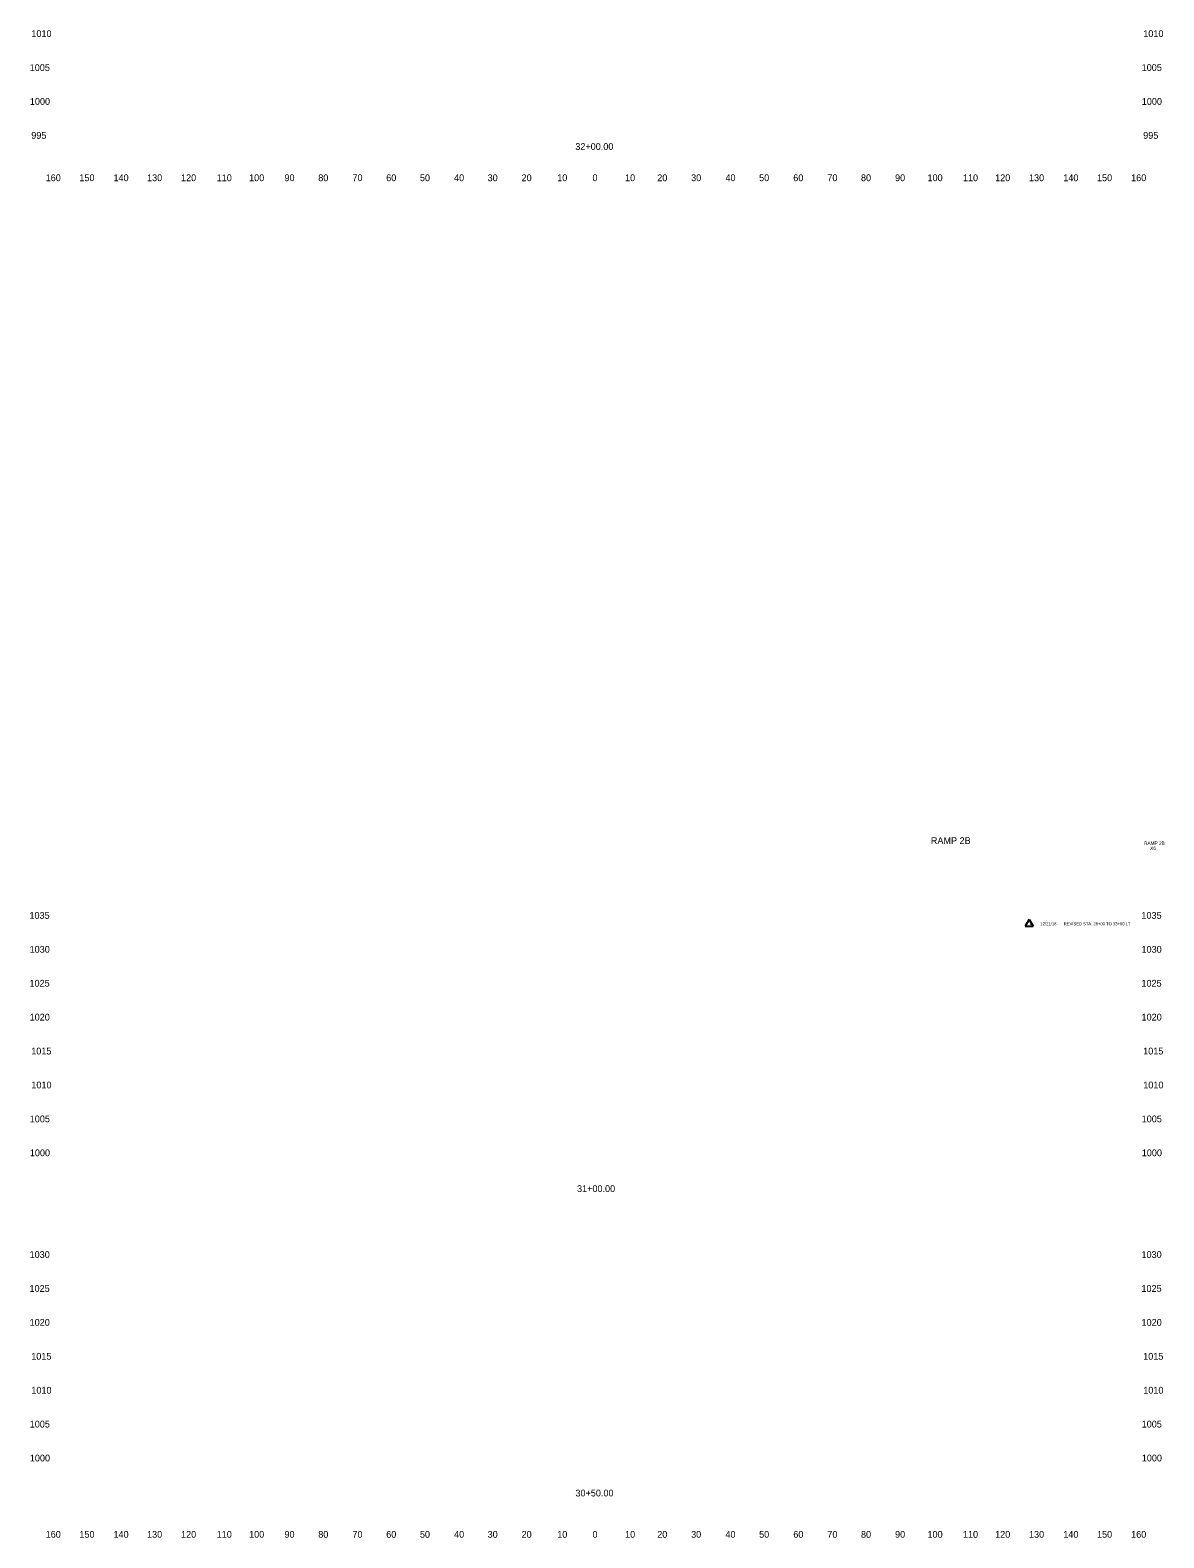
# Model space of a CAD drawing. Extents: x 4994 to 6358, y 4997 to 8804.
# Drawn here: x 4993.5 to 5327.7, y 6997.5 to 7442 of the extents above; entities that cross this region are included whole.
import ezdxf

# ---------------------------------------------------------------- set-up
doc = ezdxf.new("R2010")
doc.units = 0
for name, color, linetype in [('RD_SHT_ID', 7, 'Continuous'), ('RD_SHT_TX', 7, 'Continuous'), ('RD_XS_TX_Offset', 7, 'Continuous'), ('RD_XS_TX_Station', 7, 'Continuous')]:
    doc.layers.add(name, color=color, linetype=linetype)

msp = doc.modelspace()

# ---------------------------------------------------------------- linework, layer by layer
at = {"layer": 'RD_SHT_TX'}
for p, q in [((5288.05, 7179.83), (5286.91, 7177.8)), ((5288.05, 7179.83), (5289.19, 7177.8)), ((5286.91, 7177.8), (5289.19, 7177.8))]:
    msp.add_line(p, q, dxfattribs=at)

# ---------------------------------------------------------------- texts
at = {"layer": 'RD_SHT_ID'}
for s, height, p in [('RAMP 2B', 2, (5259.05, 7202.06)), ('RAMP 2B', 1, (5321.94, 7201.8)), ('X6', 1, (5323.71, 7200.3))]:
    msp.add_text(s, height=height, dxfattribs=at).set_placement(p)
at = {"layer": 'RD_SHT_TX'}
for s, p in [('1', (5288.05, 7178.13)), ('12/21/18', (5291.35, 7178.12)), ('REVISED STA. 28+00 TO 33+00 LT', (5298.25, 7178.09))]:
    msp.add_text(s, height=0.88, dxfattribs=at).set_placement(p)
at = {"layer": 'RD_XS_TX_Offset'}
for s, p in [('1010', (4993.88, 7440)), ('1010', (5321.68, 7440)), ('1005', (4993.4, 7430)), ('1005', (5321.2, 7430)), ('1000', (4993.44, 7420)), ('1000', (5321.24, 7420)), ('995', (4993.86, 7410)), ('995', (5321.66, 7410)), ('160', (4998.1, 7397.5)), ('150', (5008.04, 7397.5)), ('140', (5018.1, 7397.5)), ('130', (5027.99, 7397.5)), ('120', (5038.01, 7397.5)), ('110', (5048.51, 7397.5)), ('100', (5058.07, 7397.5)), ('90', (5068.5, 7397.5)), ('80', (5078.46, 7397.5)), ('70', (5088.54, 7397.5)), ('60', (5098.5, 7397.5)), ('50', (5108.43, 7397.5)), ('40', (5118.5, 7397.5)), ('30', (5128.39, 7397.5)), ('20', (5138.4, 7397.5)), ('10', (5148.91, 7397.5)), ('0', (5159.3, 7397.5)), ('0', (5159.3, 7397.5)), ('10', (5168.91, 7397.5)), ('20', (5178.4, 7397.5)), ('30', (5188.39, 7397.5)), ('40', (5198.5, 7397.5)), ('50', (5208.43, 7397.5)), ('60', (5218.5, 7397.5)), ('70', (5228.54, 7397.5)), ('80', (5238.46, 7397.5)), ('90', (5248.5, 7397.5)), ('100', (5258.07, 7397.5)), ('110', (5268.51, 7397.5)), ('120', (5278.01, 7397.5)), ('130', (5287.99, 7397.5)), ('140', (5298.1, 7397.5)), ('150', (5308.04, 7397.5)), ('160', (5318.1, 7397.5)), ('1035', (4993.33, 7180)), ('1035', (5321.13, 7180)), ('1030', (4993.36, 7170)), ('1030', (5321.16, 7170)), ('1025', (4993.34, 7160)), ('1025', (5321.14, 7160)), ('1020', (4993.37, 7150)), ('1020', (5321.17, 7150)), ('1015', (4993.85, 7140)), ('1015', (5321.65, 7140)), ('1010', (4993.88, 7130)), ('1010', (5321.68, 7130)), ('1005', (4993.4, 7120)), ('1005', (5321.2, 7120)), ('1000', (4993.44, 7110)), ('1000', (5321.24, 7110)), ('1030', (4993.36, 7080)), ('1030', (5321.16, 7080)), ('1025', (4993.34, 7070)), ('1025', (5321.14, 7070)), ('1020', (4993.37, 7060)), ('1020', (5321.17, 7060)), ('1015', (4993.85, 7050)), ('1015', (5321.65, 7050)), ('1010', (4993.88, 7040)), ('1010', (5321.68, 7040)), ('1005', (4993.4, 7030)), ('1005', (5321.2, 7030)), ('1000', (4993.44, 7020)), ('1000', (5321.24, 7020)), ('160', (4998.1, 6997.5)), ('150', (5008.04, 6997.5)), ('140', (5018.1, 6997.5)), ('130', (5027.99, 6997.5)), ('120', (5038.01, 6997.5)), ('110', (5048.51, 6997.5)), ('100', (5058.07, 6997.5)), ('90', (5068.5, 6997.5)), ('80', (5078.46, 6997.5)), ('70', (5088.54, 6997.5)), ('60', (5098.5, 6997.5)), ('50', (5108.43, 6997.5)), ('40', (5118.5, 6997.5)), ('30', (5128.39, 6997.5)), ('20', (5138.4, 6997.5)), ('10', (5148.91, 6997.5)), ('0', (5159.3, 6997.5)), ('0', (5159.3, 6997.5)), ('10', (5168.91, 6997.5)), ('20', (5178.4, 6997.5)), ('30', (5188.39, 6997.5)), ('40', (5198.5, 6997.5)), ('50', (5208.43, 6997.5)), ('60', (5218.5, 6997.5)), ('70', (5228.54, 6997.5)), ('80', (5238.46, 6997.5)), ('90', (5248.5, 6997.5)), ('100', (5258.07, 6997.5)), ('110', (5268.51, 6997.5)), ('120', (5278.01, 6997.5)), ('130', (5287.99, 6997.5)), ('140', (5298.1, 6997.5)), ('150', (5308.04, 6997.5)), ('160', (5318.1, 6997.5))]:
    msp.add_text(s, height=2, dxfattribs=at).set_placement(p)
at = {"layer": 'RD_XS_TX_Station'}
for s, p in [('32+00.00', (5154.24, 7406.71)), ('31+00.00', (5154.75, 7099.44)), ('30+50.00', (5154.28, 7009.68))]:
    msp.add_text(s, height=2, dxfattribs=at).set_placement(p)

doc.saveas('drawing.dxf')
